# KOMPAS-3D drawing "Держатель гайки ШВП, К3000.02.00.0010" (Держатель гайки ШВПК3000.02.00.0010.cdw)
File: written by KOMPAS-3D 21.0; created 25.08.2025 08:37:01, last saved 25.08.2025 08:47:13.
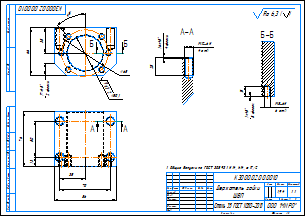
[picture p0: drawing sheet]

Sheet 1: A3, landscape

Document properties: Полное имя файла: C:\Users\ShavarinML\Desktop\Стапель\2D\Держатель гайки ШВПК3000.02.00.0010.cdw; Автор: admin; Знак неуказанной шероховатости: 4; Параметр неуказанной шероховатости: Ra 6,3; Масса: 1.935595

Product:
- Part/product: Держатель гайки ШВП  | designation К3000.02.00.0010
    Материал: Сталь 35 ГОСТ 1050-2013 (density 7826 kg/m3)
    Масса: 1.935595
  - Body: Тело 2
      Масса: 1.935905

Title block, sheet 1: Наименование: Держатель гайки / ШВП; designation: К3000.02.00.0010; Материал: Сталь 35 ГОСТ 1050-2013; Масса: 1,94; Количество листов документа: 1; organisation: ООО "МИРО"; Форматы листов документа: A3

Views: Спереди 1, Спереди, Проекционный вид 2, Разрез А-А, Разрез Б-Б, Вид:1
Referenced files in C:\Users\ShavarinML\Desktop\Стапель\Задняя бабака\Из трубы\: Обойма 3.m3d
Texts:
  Ra 3,2
  Ra 6,3
  Ra 6,3 ( )
  К3000.02.00.0010 Держатель гайки ШВП
Dimensions and other numbers on the sheet: 66; 17; 2 фаски; 65; 50,1; 35; 50; 13; 70; 76; 86; 1,6; 4 фаски; 25; -6H; 12; 4 отв.; 1; 8 фасок; 15; 8; 6 отв.; 2; 1:1; 1,94

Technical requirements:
  Общие допуски по ГОСТ 30893.1: H14, h14,   IT/2.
